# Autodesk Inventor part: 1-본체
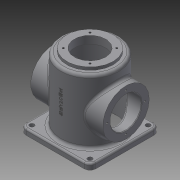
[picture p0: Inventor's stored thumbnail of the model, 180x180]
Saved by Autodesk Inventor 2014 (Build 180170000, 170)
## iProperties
Created: 2015-10
Part Number: 1-본체
Material: 일반
Document SubType Name: Modeling
Designer: Administrator
Density: 1 g/cm^3
Appearance: 기본값
Author: Administrator
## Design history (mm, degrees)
sketch "스케치1"
  geometry: C1 r 50 at (0, 0); 1 further point
  constraints: 1 centre point, 1 coincident
  dimensions: "d0" = 100 diameter of C1
extrude "돌출1" new body sketch "스케치1" distance "d1" = 120; taper "d2" = 0 deg
sketch "스케치2"
  geometry: C1 r 40 at (0, 0); 1 further point
  constraints: 1 centre point, 1 coincident
  dimensions: "d3" = 80 diameter of C1
extrude "돌출2" join sketch "스케치2" distance "d4" = 5 (computed from d1); taper "d5" = 0 deg
sketch "스케치4"
  geometry: L1 (-60, 60)-(60, 60); L2 (60, 60)-(60, -60); L3 (60, -60)-(-60, -60); L4 (-60, -60)-(-60, 60); 3 further points
  constraints: 8 end point, 2 midpoint, 2 parallel, 2 perpendicular, 1 horizontal, 1 horizontal alignment, 1 vertical alignment
  dimensions: "d28" = 120 distance of L1.start L1.end
extrude "돌출4" join sketch "스케치4" distance "d29" = 10; taper "d30" = 0 deg
sketch "스케치8"
  geometry: C1 r 40 at (0, 60); 1 further point
  constraints: 1 centre point, 1 vertical alignment
  dimensions: "d39" = 80 diameter of C1; "d40" = 60 distance of point (0, 0) C1.centre
extrude "돌출5" join sketch "스케치8" stored distance "d41" = 124; taper "d42" = 0 deg
node "작업 평면4"
sketch "스케치10"
  geometry: L1 (-3.002, 49.261)-(-3.002, 90.739); L2 (-3.002, 90.739)-(3.002, 90.739); L3 (3.002, 90.739)-(3.002, 49.261); L4 (3.002, 49.261)-(-3.002, 49.261); L5 (60, 0)-(-60, 0) reference; 4 further points
  constraints: 3 midpoint, 1 vertical alignment, 2 other
  dimensions: "d43" = 70 distance from line of L5 point (-3.002, 70)
feature "엠보싱2" sketch "스케치10" dims "d39" = 80, "d40" = 60, "d44" = 0.5, "d45" = 0
hole "구멍3" diameter "d48" = 54; stored, may be unused: countersink angle "d52" = 90 deg, drill point angle "d54" = 118 deg; dims "d46" = 10, "d47" = 10, "d49" = 6, "d50" = 90, "d51" = 112, "d53" = 8
hole "구멍4" diameter "d57" = 54; stored, may be unused: countersink angle "d61" = 90 deg, drill point angle "d63" = 118 deg; dims "d58" = 6, "d59" = 90, "d60" = 112, "d62" = 8, "d64" = 10, "d65" = 10
fillet "모깎기2" dims "d66" = 10
fillet "모깎기3" dims "d67" = 5
fillet "모깎기4" dims "d68" = 3
chamfer "모따기1" distance "d69" = 3; stored, may be unused: second distance "d70" = 2, angle "d71" = 45 deg
sketch "스케치11"
  geometry: L1 (0, 0)-(-32.5, 0); L2 (60, -50)-(60, 50) reference; 1 further point
  constraints: 2 end point, 1 horizontal, 1 horizontal alignment
  dimensions: "d72" = 32.5 distance of L1.start L1.end; "d73" = 60 distance from line of L1.start L2
hole "구멍5" sketch "스케치11" at (-32.5, 0) diameter "d74" = 3.242; stored, may be unused: countersink angle "d78" = 90 deg, drill point angle "d80" = 118 deg; dims "d75" = 8, "d76" = 90, "d77" = 112, "d79" = 10
sketch "스케치12"
  geometry: L1 (0, 0)-(-22.981, 22.981); L2 (0, -84)-(0, 84) reference
  constraints: 2 end point
  dimensions: "d85" = 45 deg angle of L2 L1; "d86" = 32.5 distance of L1.start L1.end
hole "구멍6" sketch "스케치12" at (-22.981, 22.981) diameter "d87" = 3.242; stored, may be unused: countersink angle "d91" = 90 deg, drill point angle "d93" = 118 deg; dims "d88" = 8, "d89" = 90, "d90" = 112, "d92" = 10
chamfer "모따기2" distance "d97" = 1; stored, may be unused: second distance "d98" = 2, angle "d99" = 45 deg
fillet "모깎기5" dims "d100" = 3
hole "구멍7" diameter "d103" = 8; stored, may be unused: countersink angle "d107" = 90 deg, drill point angle "d109" = 118 deg; dims "d101" = 10, "d102" = 10, "d104" = 8, "d105" = 90, "d106" = 112, "d108" = 10
hole "구멍8" diameter "d112" = 8; stored, may be unused: countersink angle "d116" = 90 deg, drill point angle "d118" = 118 deg; dims "d110" = 10, "d111" = 10, "d113" = 8, "d114" = 90, "d115" = 112, "d117" = 10
hole "구멍9" diameter "d121" = 8; stored, may be unused: countersink angle "d125" = 90 deg, drill point angle "d127" = 118 deg; dims "d119" = 10, "d120" = 10, "d122" = 8, "d123" = 90, "d124" = 112, "d126" = 10
hole "구멍10" diameter "d130" = 8; stored, may be unused: countersink angle "d134" = 90 deg, drill point angle "d136" = 118 deg; dims "d128" = 10, "d129" = 10, "d131" = 8, "d132" = 90, "d133" = 112, "d135" = 10
node "솔리드1"
pattern_circular "원형 패턴1" dims angle "d82" = 360 deg
mirror "대칭1"
pattern_circular "원형 패턴2" dims angle "d95" = 360 deg
